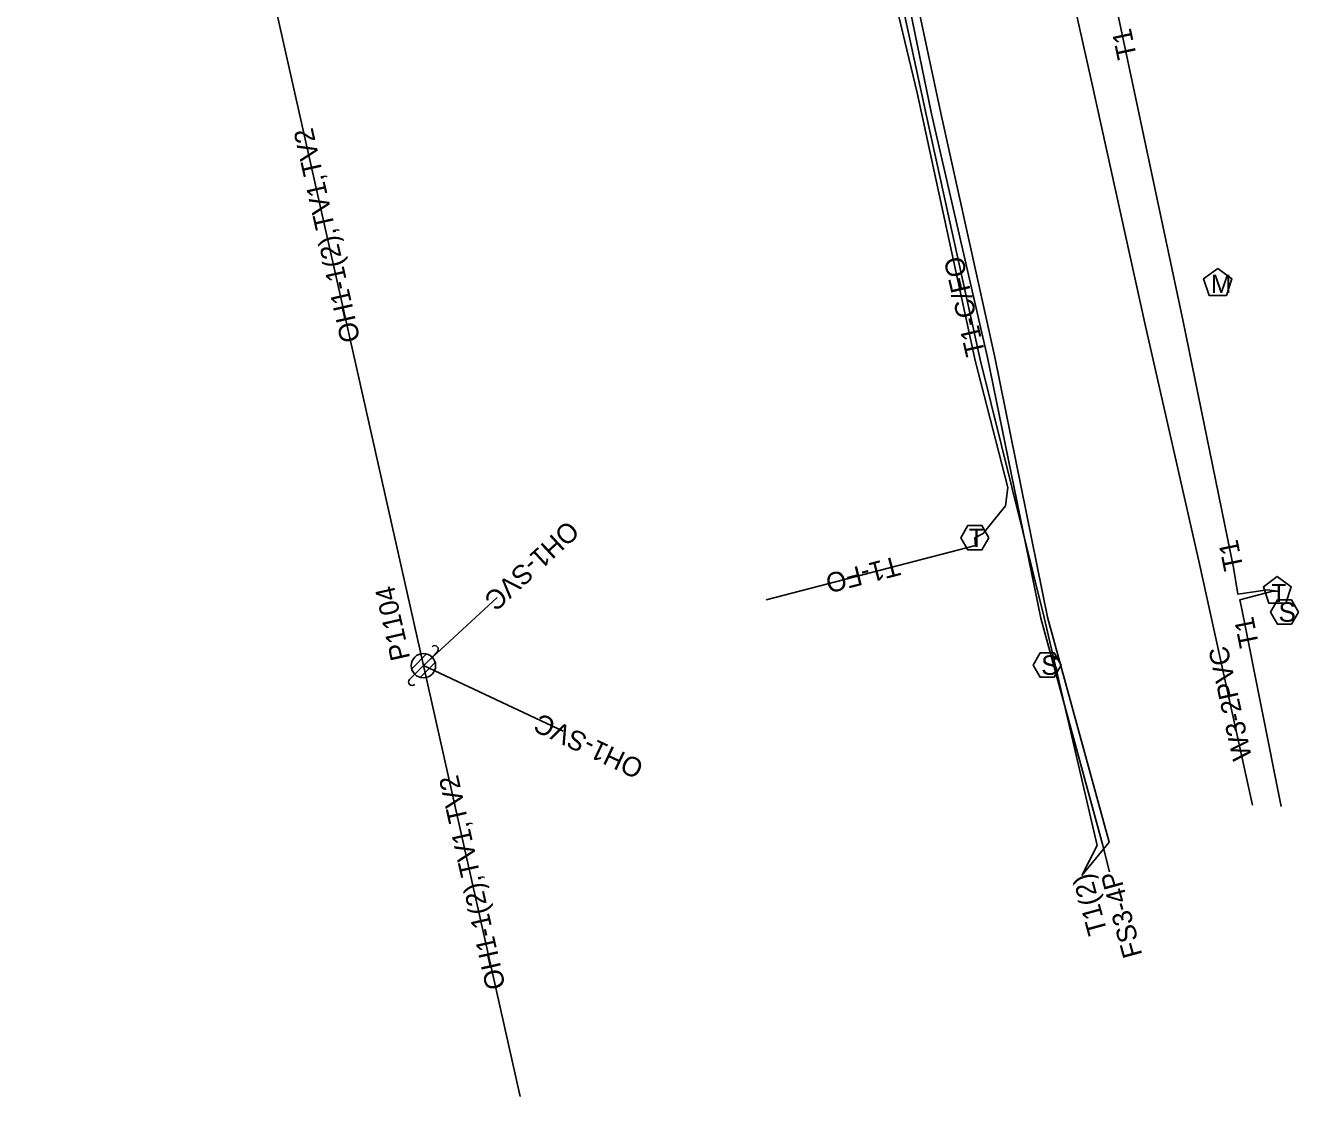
# Model space of a CAD drawing. Extents: x 2336688 to 2352634, y 362473 to 369571.
# Drawn here: x 2345598.6 to 2345860.1, y 366491.8 to 366711.7 of the extents above; entities that cross this region are included whole.
import ezdxf

# ---------------------------------------------------------------- set-up
doc = ezdxf.new("R2010")
doc.units = 0
for name, color, linetype in [('RD_EX_DV_TX_Prop', 7, 'Continuous'), ('RD_EX_RW', 7, 'Continuous'), ('RD_EX_RW_TX', 7, 'Continuous'), ('RD_HC_Data_Tic', 7, 'Continuous'), ('RD_PD_CstnLmt', 7, 'Continuous'), ('RD_PD_PatLn4', 7, 'Continuous'), ('RD_SHT_ShtClip', 7, 'Continuous'), ('RD_Sketch1', 7, 'Continuous'), ('RD_Sketch2', 7, 'Continuous'), ('RD_Sketch5', 7, 'Continuous')]:
    doc.layers.add(name, color=color, linetype=linetype)

msp = doc.modelspace()

# ---------------------------------------------------------------- linework, layer by layer
at = {"layer": 'RD_EX_RW'}
for q in [(2345821.21, 366544.02), (2345818.75, 366543.34)]:
    msp.add_line((2345815.58, 366537.19), q, dxfattribs=at)
at = {"layer": 'RD_EX_RW_TX'}
for points in [[(2345750.74, 366593.81), (2345793.71, 366604.91), (2345793.6, 366606.53), (2345795.31, 366607.4), (2345799.9, 366613.11), (2345800.37, 366616.85), (2345793.67, 366642.96), (2345781.73, 366697.86), (2345770.41, 366745.28), (2345760, 366792.61), (2345749.03, 366840.68), (2345738.69, 366890.47), (2345722.69, 366945), (2345712.84, 366986.7), (2345705.27, 367002.76), (2345702.43, 367019.22), (2345698.82, 367022.22), (2345694.02, 367020.8), (2345671.99, 367014.3), (2345636.25, 366999.09), (2345612.16, 366985.56), (2345599.72, 366974.65), (2345598.65, 366970.42), (2345599.12, 366968.34)], [(2345612.48, 366981.87), (2345613.56, 366981.96), (2345638.84, 366994.67), (2345674.13, 367006.57), (2345692.49, 367009.56), (2345702.05, 367008.67), (2345707.41, 367006.4), (2345713.56, 366986.96), (2345725.76, 366945.42), (2345739.18, 366890.21), (2345751.26, 366841.1), (2345761.25, 366792.95), (2345772.3, 366745.59), (2345783.61, 366693.46), (2345794.68, 366643.14), (2345807.85, 366590.13), (2345818.75, 366543.34)], [(2345612.48, 366981.87), (2345612.77, 366981.03), (2345614.7, 366978.36), (2345642.03, 366986.89), (2345710.46, 367003.43), (2345714.81, 367000.95), (2345717.61, 366987.66), (2345728.58, 366946.26), (2345742.57, 366890.63), (2345754.16, 366841.7), (2345765.23, 366793.37), (2345775.39, 366746.33), (2345786.64, 366693.71), (2345797.72, 366643.63), (2345808.54, 366590.2), (2345821.21, 366544.02)], [(2345856.53, 366551.35), (2345848.37, 366592.23), (2345848.01, 366593.78), (2345854.54, 366595.47), (2345855.72, 366595.54), (2345853.67, 366595.82), (2345847.63, 366594.93), (2345846.69, 366600.45), (2345836.4, 366650.92), (2345822.92, 366714.36), (2345801.14, 366799.7), (2345790.37, 366849.7), (2345779.17, 366898.83), (2345776.52, 366913.54), (2345784.01, 366915.26), (2345785.05, 366915.36)]]:
    msp.add_lwpolyline(points, dxfattribs=at)
for points in [[(2345796.48, 366606.53), (2345795.04, 366609.03), (2345792.15, 366609.03), (2345790.71, 366606.53), (2345792.15, 366604.03), (2345795.04, 366604.03)], [(2345855.72, 366598.54), (2345852.86, 366596.47), (2345853.95, 366593.11), (2345857.48, 366593.11), (2345858.57, 366596.47)]]:
    msp.add_lwpolyline(points, close=True, dxfattribs=at)
at = {"layer": 'RD_HC_Data_Tic'}
for p, q in [((2345677.96, 366579.63), (2345681.02, 366582.69)), ((2345678.6, 366578.51), (2345682.14, 366582.04)), ((2345682.14, 366582.04), (2345683.2, 366583.1)), ((2345679.72, 366577.86), (2345682.79, 366580.92)), ((2345677.54, 366577.45), (2345678.6, 366578.51))]:
    msp.add_line(p, q, dxfattribs=at)
msp.add_circle((2345680.37, 366580.27), 2.5, dxfattribs=at)
for centre, start, end in [((2345682.67, 366583.63), 315, 135), ((2345678.07, 366576.92), 135, 315)]:
    msp.add_arc(centre, 0.75, start, end, dxfattribs=at)
at = {"layer": 'RD_SHT_ShtClip'}
for p, q in [((2345680.37, 366580.27), (2345640.6, 366757.4)), ((2345680.37, 366580.27), (2345695.53, 366594.24)), ((2345700.24, 366491.79), (2345680.37, 366580.27)), ((2345680.37, 366580.27), (2345709.04, 366566.81))]:
    msp.add_line(p, q, dxfattribs=at)
at = {"layer": 'RD_Sketch1'}
msp.add_line((2345821.29, 366537.95), (2345819.85, 366543.64), dxfattribs=at)
at = {"layer": 'RD_Sketch2'}
msp.add_lwpolyline([(2345734.3, 367142.33), (2345734.6, 367138.65), (2345736.14, 367125.25), (2345743.53, 367053.85), (2345754.56, 366998.53), (2345763.65, 366947.65), (2345773.38, 366898.37), (2345784.57, 366849.11), (2345798.12, 366787.05), (2345817.62, 366699.96), (2345828.5, 366650.59), (2345839.82, 366600.83), (2345850.62, 366551.62)], dxfattribs=at)
msp.add_lwpolyline([(2345843.49, 366661.81), (2345840.59, 366659.7), (2345841.7, 366656.29), (2345845.28, 366656.29), (2345846.39, 366659.7)], close=True, dxfattribs=at)
at = {"layer": 'RD_Sketch5'}
msp.add_lwpolyline([(2345698.01, 367025), (2345698.55, 367022.93), (2345705.27, 367005.26), (2345711.96, 366986.54), (2345727.6, 366946), (2345743.93, 366891.21), (2345756.59, 366841.99), (2345763.32, 366793.48), (2345773.98, 366745.9), (2345784.68, 366693.55), (2345796.23, 366643.51), (2345807.18, 366590.01), (2345819.85, 366543.64)], dxfattribs=at)
for points in [[(2345860.08, 366591.28), (2345858.63, 366593.78), (2345855.74, 366593.78), (2345854.3, 366591.28), (2345855.74, 366588.77), (2345858.63, 366588.77)], [(2345811.33, 366580.38), (2345809.89, 366582.88), (2345807, 366582.88), (2345805.56, 366580.38), (2345807, 366577.88), (2345809.89, 366577.88)]]:
    msp.add_lwpolyline(points, close=True, dxfattribs=at)

# ---------------------------------------------------------------- texts
at = {"layer": 'RD_EX_DV_TX_Prop'}
msp.add_text('P1104', height=4, rotation=102.6564, dxfattribs=at).set_placement((2345677.67, 366581.81))
at = {"layer": 'RD_EX_RW'}
for s, rotation, p in [('T1', 101.9954, (2345826.9, 366705.24)), ('T1-C/FO', 103.0055, (2345795.76, 366644.32)), ('T1', 101.5246, (2345848.77, 366600.23)), ('T1-FO', 194.4836, (2345777.6, 366602.81)), ('T1', 101.2965, (2345851.96, 366584.42)), ('T1(2)', 105.3514, (2345820.85, 366525.57))]:
    msp.add_text(s, height=4, rotation=rotation, dxfattribs=at).set_placement(p)
at = {"layer": 'RD_EX_RW_TX'}
for p in [(2345792.39, 366604.66), (2345854.49, 366593.31)]:
    msp.add_text('T', height=3.75, dxfattribs=at).set_placement(p)
at = {"layer": 'RD_PD_CstnLmt'}
msp.add_text('W3-2PVC', height=4, rotation=102.3771, dxfattribs=at).set_placement((2345850.54, 366561.31))
at = {"layer": 'RD_PD_PatLn4'}
for s, rotation, p in [('OH1-1(2),TV1,TV2', 102.6564, (2345667.41, 366647.12)), ('OH1-SVC', 222.6517, (2345710.02, 366610.31)), ('OH1-SVC', 154.8434, (2345725.9, 366560.48)), ('OH1-1(2),TV1,TV2', 102.6564, (2345697.25, 366514.24))]:
    msp.add_text(s, height=4, rotation=rotation, dxfattribs=at).set_placement(p)
at = {"layer": 'RD_Sketch1'}
msp.add_text('FS3-4P', height=4, rotation=105.2803, dxfattribs=at).set_placement((2345828.03, 366520.88))
at = {"layer": 'RD_Sketch2'}
msp.add_text('M', height=3.75, dxfattribs=at).set_placement((2345842.12, 366656.77))
at = {"layer": 'RD_Sketch5'}
for p in [(2345855.96, 366589.28), (2345807.22, 366578.38)]:
    msp.add_text('S', height=4, dxfattribs=at).set_placement(p)

doc.saveas('drawing.dxf')
